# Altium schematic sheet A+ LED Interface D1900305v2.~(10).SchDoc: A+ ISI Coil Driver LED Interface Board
size A; Address2: California Institute of; Address3: Technology; DocumentNumber: D1900305; Revision: v2; SheetNumber: 1; SheetTotal: 1; PageSetup: Record=PageOptions¦CenterHorizontal=True¦CenterVertical=True¦PrintScale=1.38¦XCorrection=1.00¦YCorrection=1.00¦PrintKind=1¦BorderSize=5000000¦LeftOffset=0¦BottomOffset=0¦Orientation=2¦PaperLength=1000¦PaperWidth=1000¦Scale=100¦PaperSource=15¦PrintQuality=600¦MediaType=1¦DitherType=10¦PaperKind=11x17¦PrintScaleMode=1
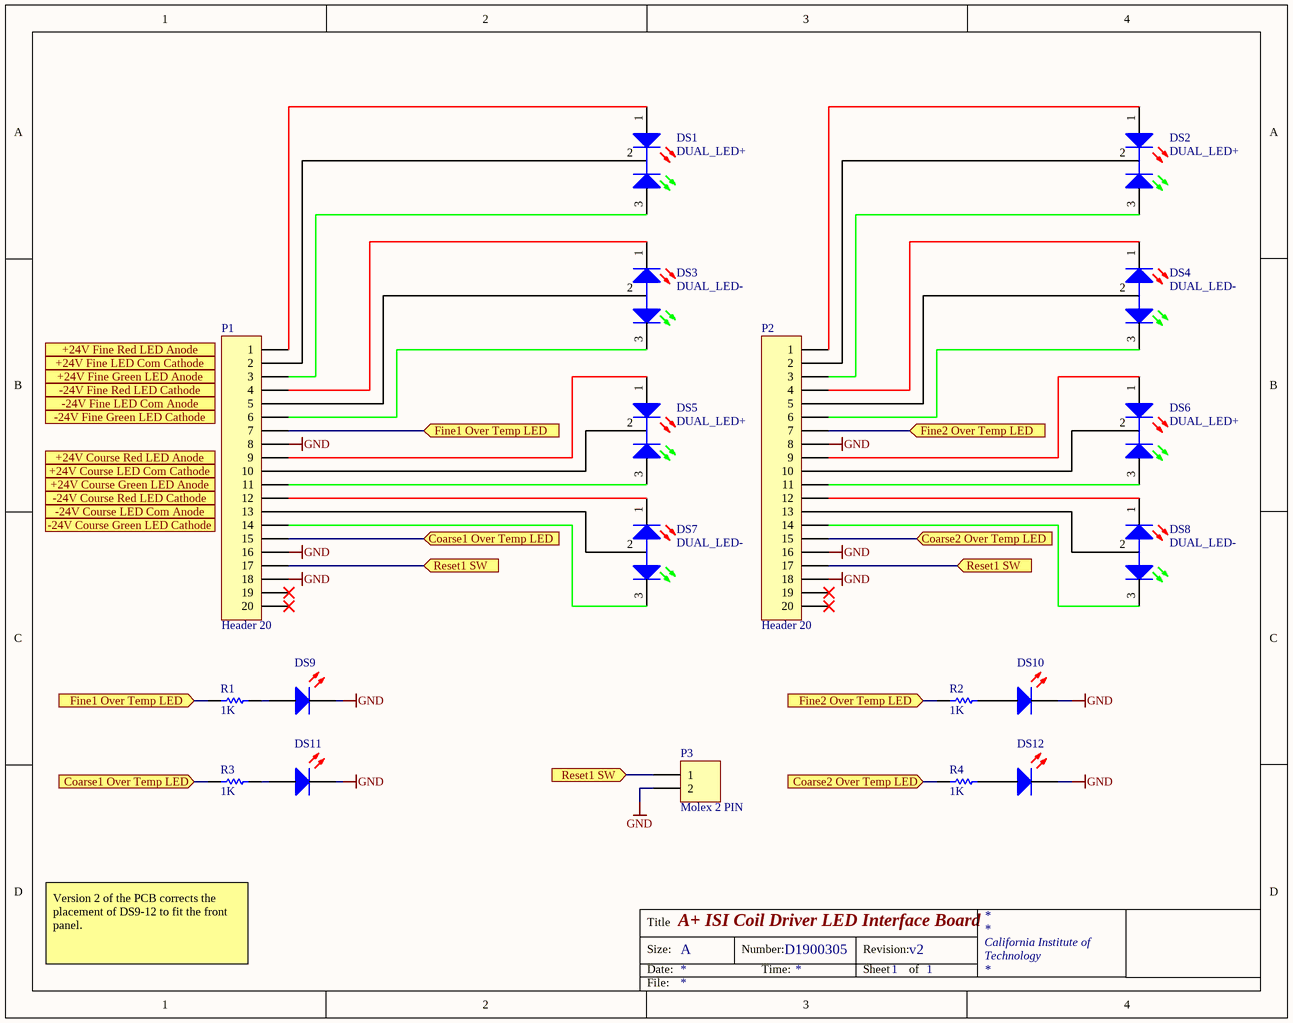
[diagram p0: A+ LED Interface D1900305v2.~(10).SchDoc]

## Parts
DS1  DUAL_LED+  [COM_CATHODE LED]
DS2  DUAL_LED+  [COM_CATHODE LED]
DS3  DUAL_LED-  [LED R/G Comm Anode (+)]
DS4  DUAL_LED-  [LED R/G Comm Anode (+)]
DS5  DUAL_LED+  [COM_CATHODE LED]
DS6  DUAL_LED+  [LED R/G COMM CATHODE (-)]
DS7  DUAL_LED-  [LED R/G Comm Anode (+)]
DS8  DUAL_LED-  [LED R/G Comm Anode (+)]
DS9  LED0  [RED_led]  (value not drawn)
DS10  LED0  [RED_led]  (value not drawn)
DS11  LED0  [RED_led]  (value not drawn)
DS12  LED0  [RED_led]  (value not drawn)
P1  Header 20  [IDC 20 _Vertical]
P2  Header 20  [IDC 20 _Vertical]
P3  Molex 2 PIN  [2Pin_Molex 100 mil]
R1  1K  [3216[1206]]
R2  1K  [3216[1206]]
R3  1K  [3216[1206]]
R4  1K  [3216[1206]]

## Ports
+24V Course Green LED Anode, +24V Course LED Com Cathode, +24V Course Red LED Anode, +24V Fine Green LED Anode, +24V Fine LED Com Cathode, +24V Fine Red LED Anode, -24V Course Green LED Cathode, -24V Course LED Com Anode, -24V Course Red LED Cathode, -24V Fine Green LED Cathode, -24V Fine LED Com Anode, -24V Fine Red LED Cathode, Coarse1 Over Temp LED (in), Coarse2 Over Temp LED (in), Fine1 Over Temp LED (in), Fine2 Over Temp LED (in), Reset1 SW (in)

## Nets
GND: DS9.2(K) DS10.2(K) DS11.2(K) DS12.2(K) P1.8 P1.16 P1.18 P2.8 P2.16 P2.18 P3.2
Coarse1 Over Temp LED: P1.15 R3.1 ; port Coarse1 Over Temp LED
Coarse2 Over Temp LED: P2.15 R4.1 ; port Coarse2 Over Temp LED
Fine1 Over Temp LED: P1.7 R1.1 ; port Fine1 Over Temp LED
Fine2 Over Temp LED: P2.7 R2.1 ; port Fine2 Over Temp LED
Reset1 SW: P1.17 P2.17 P3.1 ; port Reset1 SW
NetDS1_1: DS1.1(A) P1.1
NetDS1_2: DS1.2(K) P1.2
NetDS1_3: DS1.3(A) P1.3
NetDS2_1: DS2.1(A) P2.1
NetDS2_2: DS2.2(K) P2.2
NetDS2_3: DS2.3(A) P2.3
NetDS3_1: DS3.1(A) P1.4
NetDS3_2: DS3.2(K) P1.5
NetDS3_3: DS3.3(A) P1.6
NetDS4_1: DS4.1(A) P2.4
NetDS4_2: DS4.2(K) P2.5
NetDS4_3: DS4.3(A) P2.6
NetDS5_1: DS5.1(A) P1.9
NetDS5_2: DS5.2(K) P1.10
NetDS5_3: DS5.3(A) P1.11
NetDS6_1: DS6.1(A) P2.9
NetDS6_2: DS6.2(K) P2.10
NetDS6_3: DS6.3(A) P2.11
NetDS7_1: DS7.1(A) P1.12
NetDS7_2: DS7.2(K) P1.13
NetDS7_3: DS7.3(A) P1.14
NetDS8_1: DS8.1(A) P2.12
NetDS8_2: DS8.2(K) P2.13
NetDS8_3: DS8.3(A) P2.14
NetDS9_1: DS9.1(A) R1.2
NetDS10_1: DS10.1(A) R2.2
NetDS11_1: DS11.1(A) R3.2
NetDS12_1: DS12.1(A) R4.2

Not connected (* = marked no-connect by the designer): P1 19* 20*; P2 19* 20*

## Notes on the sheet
- Version 2 of the PCB corrects the placement of DS9-12 to fit the front panel.

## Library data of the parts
DS1 DS2 DS5 = DUAL_LED+: Green, Red  LED Indication - Discrete 2.2V Green, 2V Red Radial - 3 Leads; Manufacturer: Lumex; Manufacturer Part Number: SSL-LX3059IGW; Lens Color: White; Viewing Angle: 60°; Test Current: 20mA; Lens Style: Dome,Round,Diffused,Colorless; Luminous Intensity: 30mcd; Lens Transparency: Diffused; Dominant Wavelength: 635nm; Forward Current: 150mA; Power Dissipation: 105mW; Wavelength: 565nm; Number of LEDs: 2
DS3 DS4 DS7 DS8 = DUAL_LED Comm Anode: Green, Red  LED Indication - Discrete 2.2V Green, 2V Red Radial - 3 Leads; Manufacturer: Lumex; Manufacturer Part Number: SSL-LX3059IGW-CA; Forward Current: 20mA; Luminous Intensity: 30mcd; Lens Style: Dome,Diffused,Colorless; Viewing Angle: 60°; Wavelength: 635nm; Number of LEDs: 2; Description: LED Bi-Color Green/Red 565nm/635nm 3-Pin T-1
DS6 = DUAL_LED Comm Cathode: Green, Red  LED Indication - Discrete 2.2V Green, 2V Red Radial - 3 Leads; Manufacturer: Lumex; Manufacturer Part Number: SSL-LX3059IGW; Lens Color: White; Viewing Angle: 60°; Test Current: 20mA; Lens Style: Dome,Round,Diffused,Colorless; Luminous Intensity: 30mcd; Lens Transparency: Diffused; Dominant Wavelength: 635nm; Forward Current: 150mA; Power Dissipation: 105mW; Wavelength: 565nm; Number of LEDs: 2
DS9-DS12 = LED0: Red 640nm LED Indication - Discrete 1.85V Radial; Manufacturer: Kingbright; Manufacturer Part Number: WP710A10SRD/F; Lens Style: Dome,Diffused; Viewing Angle: 40°; Luminous Intensity: 160mcd; Test Current: 20mA; Lens Transparency: Diffused
P1 P2 = Header 20: Header, 20-Pin; Manufacturer: Amphenol FCI; Manufacturer Part Number: 71918-120LF; Current Rating: 1A; Mating Cycles: 250; Number of Poles: 20; Voltage Rating: 1.5kV; Insulation Resistance: 100GR; Gender: Male; Connector Type: Male Pin; Pitch: 2.54mm; Contact Post Length: 2.9mm; Row Spacing: 0.1inch; Hole Diameter: 1mm; Approvals: UL,CSA
P3 = Header 2H: Header, 2-Pin, Right Angle; Number of Positions: 2; Gender: Male; Contact Resistance: 10mR; Current Rating: 4A; Voltage Rating: 250V; Max Current Rating: 7A; Insulation Resistance: 50GR; Pitch: 2.54mm; Approvals: UL,CSA
R1-R4 = Res Semi: Semiconductor Resistor; Manufacturer: Panasonic; Manufacturer Part Number: ERJ-8ENF1001V; Resistance: 1kR; Tolerance: 1%; Voltage Rating: 200V; Power Rating: 250mW; Temperature Coefficient: 100ppm/°C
